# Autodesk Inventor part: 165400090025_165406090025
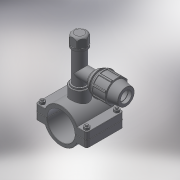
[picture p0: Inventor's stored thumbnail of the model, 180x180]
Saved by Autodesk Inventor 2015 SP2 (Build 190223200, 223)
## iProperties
Created: 2017-05
Part Number: 165400090025_165406090025
Material: Generic
Description: PLASSON TAPPER FOR PE+PVC PIPE 90-25
Document SubType Name: Modeling
Designer: KIM
Density: 1 g/cm^3
Appearance: Default
Author: KIM
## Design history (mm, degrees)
derived "16540.ipt"
feature "Solid1::16540.ipt"
feature "Solid2::16540.ipt"
tag "TaggingFeature1"
body "Solid1"
other parameters: "d0" = 99, "d1" = 141, "d2" = 45, "d4" = 105, "d5" = 0, "d6" = 7.05, "d7" = 141, "d8" = 0.1, "d10" = 0, "d11" = 0.9, "d14" = 39.3783, "d20" = 0.9, "d23" = 0.9, "d36" = 13, "d37" = 10.4, "d38" = 53, "d39" = 0, "d40" = 3, "d41" = 5, "d42" = 0, "d43" = 8, "d44" = 3, "d45" = 0, "d46" = 0.9, "d51" = 75, "d52" = 30.291, "d53" = 21, "d54" = 0, "d55" = 25, "d57" = 0, "d58" = 97.2, "d60" = 0, "d62" = 13, "d63" = 10.4, "d66" = 84.2, "d67" = 25, "d68" = 8.75, "d69" = 21, "d70" = 54, "d71" = 40.5, "d72" = 1.5, "d73" = 43.2, "d74" = 120 deg, "d75" = 37.5, "d76" = 10 deg, "d77" = 48.6, "d78" = 31.5, "d79" = 61, "d81" = 105, "d82" = 6.1, "d87" = 15, "d90" = 50.22, "d91" = 35 deg, "d92" = 17.5 deg, "d94" = 0, "d96" = 360 deg, "d98" = 0.5, "d99" = 67.1, "d100" = 27.2619, "d101" = 135 deg, "d102" = 1.08, "d105" = 2.7, "d106" = 0, "d107" = 0.1, "d108" = 27.2619, "d109" = 33.3201, "d111" = 26.2, "d112" = 6.55, "d113" = 3.5, "d116" = 0, "d118" = 21, "d119" = 0, "d121" = 131, "d122" = 58, "B_" = 25, "G_" = 30.291, "A_" = 75, "L_" = 141, "L_1" = 105, "l_2" = 21, "d_1" = 25, "E_" = 54, "l_" = 61, "H_" = 105, "H_1" = 58, "H_2" = 131
